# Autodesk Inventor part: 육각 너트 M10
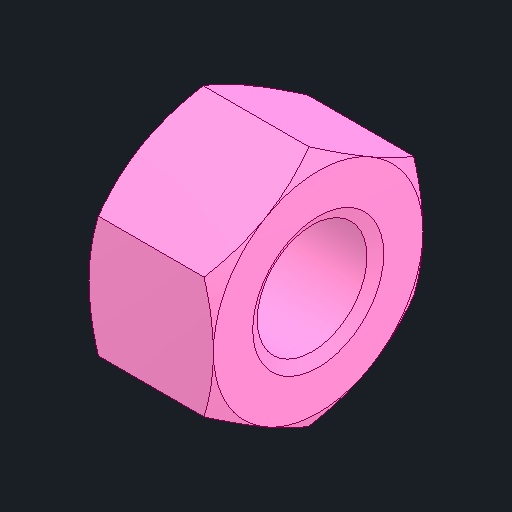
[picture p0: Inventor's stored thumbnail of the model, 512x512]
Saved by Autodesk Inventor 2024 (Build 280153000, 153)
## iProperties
Created: 2025-02
Part Number: 육각 너트 M10
Material: 강철, 연강
Description: 6각 너트 및 6각 가는 너트
Document SubType Name: Modeling
Designer: kh_501
Density: 7.85 g/cm^3
Appearance: 기본값
Author: jhkim
Sending System: Autodesk Inventor 2025
Preprocessor: ST-DEVELOPER v20
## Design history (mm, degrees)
node "육각 너트 M101"
node "솔리드1"
body "Solid1"
